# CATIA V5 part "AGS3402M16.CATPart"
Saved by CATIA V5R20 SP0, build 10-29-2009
Part number: AGS3402M16
Definition: NONE
Nomenclature: AGS3402M16
Source: Unknown
Description: AGS3402M16
Bounding box of the stored display mesh (mm): x -24 to 28, y -24 to 24, z -24 to 24
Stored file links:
  C:\Users\Utente\Desktop\IO LAVORO\3D X SITO CF\X SITO\PLASTICA\AGS\AGS3402M16.CATPart
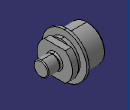
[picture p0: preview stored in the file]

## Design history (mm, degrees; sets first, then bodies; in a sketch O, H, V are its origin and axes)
Body1 "AGS3402M16" (main body)
  Solid1: solid without history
